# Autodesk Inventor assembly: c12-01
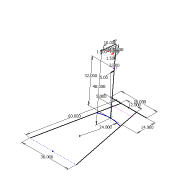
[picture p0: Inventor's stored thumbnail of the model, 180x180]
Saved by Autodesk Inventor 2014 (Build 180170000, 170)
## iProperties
Created: 2011-01
Part Number: c12-01
Document SubType Name: Assembly
Designer: Thom Tremblay
Author: Thom Tremblay
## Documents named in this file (2)
- C:\Inventor 2014 Essentials\Assemblies\Chapter 12\c12-01.iam
- C:\Inventor 2014 Essentials\Parts\Chapter 12\c12-01.ipt
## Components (1 placed, 1 different names)
1. c12-01:1
